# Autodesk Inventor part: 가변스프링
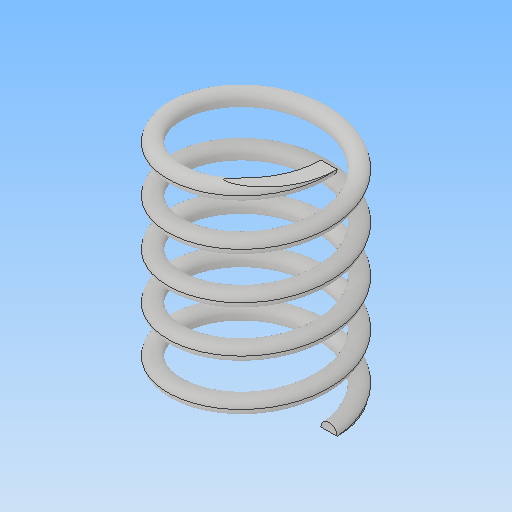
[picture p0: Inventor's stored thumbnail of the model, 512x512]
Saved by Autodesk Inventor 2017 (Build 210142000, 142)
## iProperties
Part Number: 가변스프링
Material: 일반
Document SubType Name: Modeling
Designer: MRC
Density: 1 g/cm^3
Appearance: 기본값
Mass: 0.874626 g
Surface Area: 17.7559 cm^2
Volume: 0.874626 cm^3
Author: MRC
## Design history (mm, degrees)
sketch "스케치1"
  geometry: L1 (0, 0)-(9, 0); L2 (9, 28.5)-(0, 28.5); L3 (0, 28.5)-(0, 0); C1 r 1 at (9, 0)
  constraints: 6 end point, 2 parallel, 1 centre point, 1 coincident, 1 horizontal, 1 vertical
  dimensions: "d0" = 9 distance of L1.start L1.end; "d1" = 28.5 distance of L2.end L1.start (derived); "d2" = 2 diameter of C1
feature "코일1" sketch "스케치1" pitch "d3" = 10; turns "d5" = 5; dims "d4" = 28.5 (= d1), "d6" = 0, angle "d7" = 90 deg, angle "d8" = 90 deg, "d9" = 0, "d10" = 0
sketch "스케치2"
  geometry: L1 (28.5, 20)-(0, 20); L2 (0, 20)-(0, -20); L3 (0, -20)-(28.5, -20); L4 (28.5, -20)-(28.5, 20); 2 further points
  constraints: 8 end point, 2 parallel, 1 coincident, 1 horizontal, 1 midpoint, 1 perpendicular
  dimensions: "d11" = 28.5 distance of L2.end L3.end (= d1); "d14" = 40 distance of L3.end L1.start
extrude "돌출1" sketch "스케치2" stored distance "d12" = 0; taper "d13" = 0 deg
node "솔리드1"
